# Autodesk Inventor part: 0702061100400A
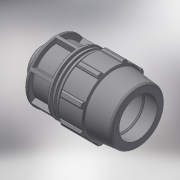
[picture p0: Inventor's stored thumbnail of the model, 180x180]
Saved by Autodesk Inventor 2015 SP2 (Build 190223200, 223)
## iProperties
Created: 2017-02
Part Number: 0702061100400A
Material: Generic
Description: PLASSON MALE ADAPTOR 110-4"
Document SubType Name: Modeling
Designer: KIM
Mass: 964.158 g
Surface Area: 1468.9 cm^2
Volume: 964.158 cm^3
Density: 1 g/cm^3
Appearance: Default
Author: KIM
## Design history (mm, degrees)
derived "87020.ipt"
feature "Solid1::87020.ipt"
tag "TaggingFeature1"
body "Solid1"
other parameters: "d4" = 37.85714, "d5" = 66.25, "d7" = 181, "d8" = 135.75, "d9" = 37.85714, "d11" = 7.57143, "d12" = 144.8, "d13" = 120 deg, "d14" = 143, "d15" = 6 deg, "d16" = 162.9, "d18" = 5.5, "d19" = 35 deg, "d20" = 17.5 deg, "d21" = 168.33, "d23" = 0, "d25" = 360 deg, "d27" = 3.62, "d34" = 9.05, "d36" = 0, "d42" = 71.55, "d43" = 5.43, "d46" = 3.3, "d49" = 213, "d51" = 265, "d52" = 42, "d53" = 2.2, "d55" = 360 deg, "d57" = 113.03, "d58" = 79.121, "d59" = 53, "d61" = 159.642, "d62" = 3.41143, "d63" = 3.41143, "d66" = 6.82286, "E_" = 181, "H_" = 265, "l_" = 213, "l_2" = 42, "R_" = 113.03, "d60" = 17.05714
